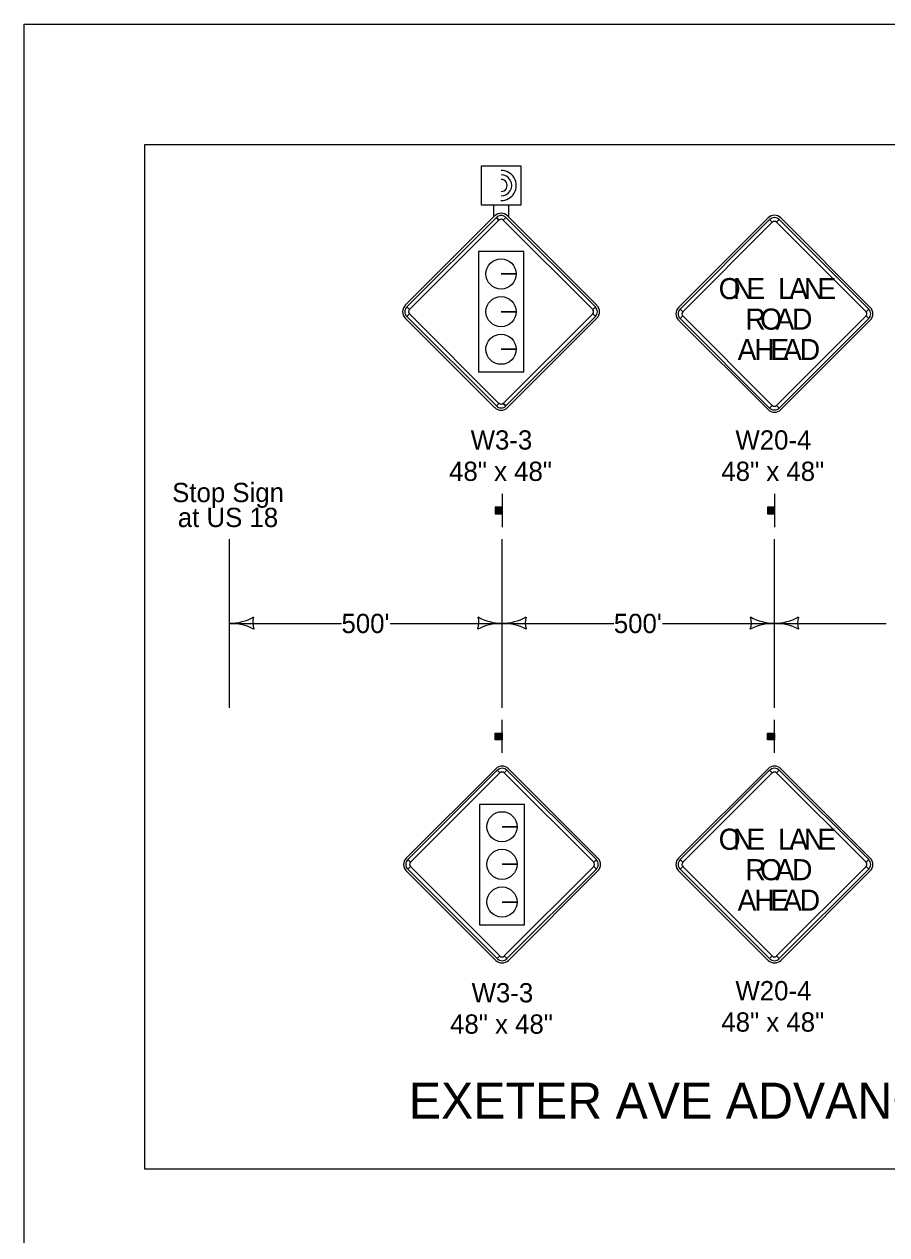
# Model space of a CAD drawing. Extents: x -2134934 to -2122394, y -2140205 to -2137036.
# Drawn here: x -2125529 to -2124814, y -2138041 to -2137036 of the extents above; entities that cross this region are included whole.
import ezdxf

# ---------------------------------------------------------------- set-up
doc = ezdxf.new("R2010")
doc.units = 0
for name, color, linetype in [('Barrier', 7, 'Continuous'), ('BridgeSuperStructureExisting', 7, 'Continuous'), ('Default', 7, 'Continuous')]:
    doc.layers.add(name, color=color, linetype=linetype)

msp = doc.modelspace()

# ---------------------------------------------------------------- linework, layer by layer
at = {"layer": 'Barrier'}
for p, q in [((-2125139.1, -2137195.1), (-2125213.3, -2137269.3)), ((-2125137.7, -2137196.4), (-2125135.5, -2137198.6)), ((-2125132, -2137198.6), (-2125129.8, -2137196.4)), ((-2125054.2, -2137269.3), (-2125128.4, -2137195.1)), ((-2124912.2, -2137196.8), (-2124986.5, -2137271.1)), ((-2124910.9, -2137198.1), (-2124908.7, -2137200.4)), ((-2124905.1, -2137200.4), (-2124902.9, -2137198.1)), ((-2124827.4, -2137271.1), (-2124901.6, -2137196.8)), ((-2125121.3, -2137243.3), (-2125133.8, -2137243.3)), ((-2125133.8, -2137243.3), (-2125121.3, -2137243.3)), ((-2125209.8, -2137272.9), (-2125212, -2137270.7)), ((-2125212, -2137278.6), (-2125209.8, -2137276.4)), ((-2125121.3, -2137274.6), (-2125133.8, -2137274.6)), ((-2125133.8, -2137274.6), (-2125121.3, -2137274.6)), ((-2125055.5, -2137270.7), (-2125057.7, -2137272.9)), ((-2125057.7, -2137276.4), (-2125055.5, -2137278.6)), ((-2124982.9, -2137274.6), (-2124985.1, -2137272.4)), ((-2124985.1, -2137280.3), (-2124982.9, -2137278.1)), ((-2124828.7, -2137272.4), (-2124830.9, -2137274.6)), ((-2124830.9, -2137278.1), (-2124828.7, -2137280.3)), ((-2125213.3, -2137280), (-2125139.1, -2137354.2)), ((-2125128.4, -2137354.2), (-2125054.2, -2137280)), ((-2124986.5, -2137281.7), (-2124912.2, -2137355.9)), ((-2124901.6, -2137355.9), (-2124827.4, -2137281.7)), ((-2125121.3, -2137305.8), (-2125133.8, -2137305.8)), ((-2125133.8, -2137305.8), (-2125121.3, -2137305.8)), ((-2125135.5, -2137350.7), (-2125137.7, -2137352.9)), ((-2125129.8, -2137352.9), (-2125132, -2137350.7)), ((-2124908.7, -2137352.4), (-2124910.9, -2137354.6)), ((-2124902.9, -2137354.6), (-2124905.1, -2137352.4)), ((-2125138.2, -2137654), (-2125212.5, -2137728.2)), ((-2125136.9, -2137655.3), (-2125134.7, -2137657.5)), ((-2125131.2, -2137657.5), (-2125129, -2137655.3)), ((-2125053.4, -2137728.2), (-2125127.6, -2137654)), ((-2124912.2, -2137654), (-2124986.5, -2137728.2)), ((-2124910.9, -2137655.3), (-2124908.7, -2137657.5)), ((-2124905.1, -2137657.5), (-2124902.9, -2137655.3)), ((-2124827.4, -2137728.2), (-2124901.6, -2137654)), ((-2125120.5, -2137702.2), (-2125133, -2137702.2)), ((-2125133, -2137702.2), (-2125120.5, -2137702.2)), ((-2125209, -2137731.7), (-2125211.2, -2137729.5)), ((-2125054.7, -2137729.5), (-2125056.9, -2137731.7)), ((-2124982.9, -2137731.7), (-2124985.1, -2137729.5)), ((-2124828.7, -2137729.5), (-2124830.9, -2137731.7)), ((-2125212.5, -2137738.8), (-2125138.2, -2137813.1)), ((-2125211.2, -2137737.5), (-2125209, -2137735.3)), ((-2125120.5, -2137733.4), (-2125133, -2137733.4)), ((-2125133, -2137733.4), (-2125120.5, -2137733.4)), ((-2125127.6, -2137813.1), (-2125053.4, -2137738.8)), ((-2125056.9, -2137735.3), (-2125054.7, -2137737.5)), ((-2124986.5, -2137738.8), (-2124912.2, -2137813.1)), ((-2124985.1, -2137737.5), (-2124982.9, -2137735.3)), ((-2124901.6, -2137813.1), (-2124827.4, -2137738.8)), ((-2124830.9, -2137735.3), (-2124828.7, -2137737.5)), ((-2125120.5, -2137764.7), (-2125133, -2137764.7)), ((-2125133, -2137764.7), (-2125120.5, -2137764.7)), ((-2125134.7, -2137809.5), (-2125136.9, -2137811.7)), ((-2125129, -2137811.7), (-2125131.2, -2137809.5)), ((-2124908.7, -2137809.5), (-2124910.9, -2137811.7)), ((-2124902.9, -2137811.7), (-2124905.1, -2137809.5))]:
    msp.add_line(p, q, dxfattribs=at)
for points in [[(-2125429.5, -2137135.9), (-2124308.2, -2137135.9), (-2124308.2, -2137986.6), (-2125429.5, -2137986.6)], [(-2125137.7, -2137196.4), (-2125212, -2137270.7), (-2125209.8, -2137272.9), (-2125135.5, -2137198.6), (-2125137.7, -2137196.4)], [(-2125055.5, -2137270.7), (-2125129.8, -2137196.4), (-2125132, -2137198.6), (-2125057.7, -2137272.9), (-2125055.5, -2137270.7)], [(-2124910.9, -2137198.1), (-2124985.1, -2137272.4), (-2124982.9, -2137274.6), (-2124908.7, -2137200.4), (-2124910.9, -2137198.1)], [(-2124828.7, -2137272.4), (-2124902.9, -2137198.1), (-2124905.1, -2137200.4), (-2124830.9, -2137274.6), (-2124828.7, -2137272.4)], [(-2125115, -2137224.7), (-2125152.5, -2137224.7), (-2125152.5, -2137324.6), (-2125115, -2137324.6), (-2125115, -2137224.7)], [(-2125212, -2137278.6), (-2125137.7, -2137352.9), (-2125135.5, -2137350.7), (-2125209.8, -2137276.4), (-2125212, -2137278.6)], [(-2125129.8, -2137352.9), (-2125055.5, -2137278.6), (-2125057.7, -2137276.4), (-2125132, -2137350.7), (-2125129.8, -2137352.9)], [(-2124985.1, -2137280.3), (-2124910.9, -2137354.6), (-2124908.7, -2137352.4), (-2124982.9, -2137278.1), (-2124985.1, -2137280.3)], [(-2124902.9, -2137354.6), (-2124828.7, -2137280.3), (-2124830.9, -2137278.1), (-2124905.1, -2137352.4), (-2124902.9, -2137354.6)], [(-2125136.9, -2137655.3), (-2125211.2, -2137729.5), (-2125209, -2137731.7), (-2125134.7, -2137657.5), (-2125136.9, -2137655.3)], [(-2125054.7, -2137729.5), (-2125129, -2137655.3), (-2125131.2, -2137657.5), (-2125056.9, -2137731.7), (-2125054.7, -2137729.5)], [(-2124910.9, -2137655.3), (-2124985.1, -2137729.5), (-2124982.9, -2137731.7), (-2124908.7, -2137657.5), (-2124910.9, -2137655.3)], [(-2124828.7, -2137729.5), (-2124902.9, -2137655.3), (-2124905.1, -2137657.5), (-2124830.9, -2137731.7), (-2124828.7, -2137729.5)], [(-2125114.2, -2137683.6), (-2125151.7, -2137683.6), (-2125151.7, -2137783.5), (-2125114.2, -2137783.5), (-2125114.2, -2137683.6)], [(-2125211.2, -2137737.5), (-2125136.9, -2137811.7), (-2125134.7, -2137809.5), (-2125209, -2137735.3), (-2125211.2, -2137737.5)], [(-2125129, -2137811.7), (-2125054.7, -2137737.5), (-2125056.9, -2137735.3), (-2125131.2, -2137809.5), (-2125129, -2137811.7)], [(-2124985.1, -2137737.5), (-2124910.9, -2137811.7), (-2124908.7, -2137809.5), (-2124982.9, -2137735.3), (-2124985.1, -2137737.5)], [(-2124902.9, -2137811.7), (-2124828.7, -2137737.5), (-2124830.9, -2137735.3), (-2124905.1, -2137809.5), (-2124902.9, -2137811.7)]]:
    msp.add_lwpolyline(points, close=True, dxfattribs=at)
for centre in [(-2125133.8, -2137243.3), (-2125133.8, -2137274.6), (-2125133.8, -2137305.8), (-2125133, -2137702.2), (-2125133, -2137733.4), (-2125133, -2137764.7)]:
    msp.add_circle(centre, 12.5, dxfattribs=at)
for centre, radius, start, end in [((-2125133.7, -2137200.4), 7.5, 45, 134.9997), ((-2125133.7, -2137200.4), 5.62, 45, 134.9997), ((-2125133.7, -2137200.4), 2.5, 45, 134.9997), ((-2124906.9, -2137202.1), 7.5, 45, 134.9997), ((-2124906.9, -2137202.1), 5.62, 45, 134.9997), ((-2124906.9, -2137202.1), 2.5, 45, 134.9997), ((-2125208, -2137274.7), 7.5, 134.9997, 225), ((-2125208, -2137274.7), 5.62, 134.9997, 225), ((-2125208, -2137274.7), 2.5, 134.9997, 225), ((-2125059.5, -2137274.7), 2.5, 315.0002, 44.9998), ((-2125059.5, -2137274.7), 5.62, 315.0002, 44.9998), ((-2125059.5, -2137274.7), 7.5, 315.0002, 44.9998), ((-2124981.2, -2137276.4), 7.5, 134.9997, 225), ((-2124981.2, -2137276.4), 5.62, 134.9997, 225), ((-2124981.2, -2137276.4), 2.5, 134.9997, 225), ((-2124832.7, -2137276.4), 2.5, 315.0002, 44.9998), ((-2124832.7, -2137276.4), 5.62, 315.0002, 44.9998), ((-2124832.7, -2137276.4), 7.5, 315.0002, 44.9998), ((-2125133.7, -2137348.9), 7.5, 225, 315.0002), ((-2125133.7, -2137348.9), 5.62, 225, 315.0002), ((-2125133.7, -2137348.9), 2.5, 225, 315.0002), ((-2124906.9, -2137350.6), 7.5, 225, 315.0002), ((-2124906.9, -2137350.6), 5.62, 225, 315.0002), ((-2124906.9, -2137350.6), 2.5, 225, 315.0002), ((-2125132.9, -2137659.3), 7.5, 45, 134.9997), ((-2125132.9, -2137659.3), 5.62, 45, 134.9997), ((-2125132.9, -2137659.3), 2.5, 45, 134.9997), ((-2124906.9, -2137659.3), 7.5, 45, 134.9997), ((-2124906.9, -2137659.3), 5.62, 45, 134.9997), ((-2124906.9, -2137659.3), 2.5, 45, 134.9997), ((-2125207.2, -2137733.5), 7.5, 134.9997, 225), ((-2125207.2, -2137733.5), 5.62, 134.9997, 225), ((-2125058.7, -2137733.5), 5.62, 315.0002, 44.9998), ((-2125058.7, -2137733.5), 7.5, 315.0002, 44.9998), ((-2124981.2, -2137733.5), 7.5, 134.9997, 225), ((-2124981.2, -2137733.5), 5.62, 134.9997, 225), ((-2124832.7, -2137733.5), 5.62, 315.0002, 44.9998), ((-2124832.7, -2137733.5), 7.5, 315.0002, 44.9998), ((-2125207.2, -2137733.5), 2.5, 134.9997, 225), ((-2125058.7, -2137733.5), 2.5, 315.0002, 44.9998), ((-2124981.2, -2137733.5), 2.5, 134.9997, 225), ((-2124832.7, -2137733.5), 2.5, 315.0002, 44.9998), ((-2125132.9, -2137807.8), 2.5, 225, 315.0002), ((-2124906.9, -2137807.8), 2.5, 225, 315.0002), ((-2125132.9, -2137807.8), 7.5, 225, 315.0002), ((-2125132.9, -2137807.8), 5.62, 225, 315.0002), ((-2124906.9, -2137807.8), 7.5, 225, 315.0002), ((-2124906.9, -2137807.8), 5.62, 225, 315.0002)]:
    msp.add_arc(centre, radius, start, end, dxfattribs=at)
at = {"layer": 'BridgeSuperStructureExisting'}
for p, q in [((-2125140, -2137186.1), (-2125140, -2137196.1)), ((-2125127.5, -2137186.1), (-2125127.5, -2137196.1)), ((-2125132.9, -2137425.9), (-2125132.9, -2137453.4)), ((-2124906.9, -2137425.9), (-2124906.9, -2137453.4)), ((-2125138.3, -2137436.8), (-2125138.3, -2137442.4)), ((-2125138, -2137442.4), (-2125138, -2137436.8)), ((-2125137.7, -2137436.8), (-2125137.7, -2137442.4)), ((-2125137.4, -2137442.4), (-2125137.4, -2137436.8)), ((-2125137.2, -2137436.8), (-2125137.2, -2137442.4)), ((-2125136.8, -2137442.4), (-2125136.8, -2137436.8)), ((-2125136.5, -2137436.8), (-2125136.5, -2137442.4)), ((-2125136.1, -2137442.4), (-2125136.1, -2137436.8)), ((-2125135.7, -2137436.8), (-2125135.7, -2137442.4)), ((-2125135.4, -2137442.4), (-2125135.4, -2137436.8)), ((-2125135.2, -2137436.8), (-2125135.2, -2137442.4)), ((-2125134.9, -2137442.4), (-2125134.9, -2137436.8)), ((-2125134.6, -2137436.8), (-2125134.6, -2137442.4)), ((-2125134.4, -2137442.4), (-2125134.4, -2137436.8)), ((-2125134.2, -2137436.8), (-2125134.2, -2137442.4)), ((-2125133.9, -2137442.4), (-2125133.9, -2137436.8)), ((-2125133.6, -2137436.8), (-2125133.6, -2137442.4)), ((-2125133.4, -2137442.4), (-2125133.4, -2137436.8)), ((-2124912.2, -2137436.8), (-2124912.2, -2137442.4)), ((-2124911.9, -2137442.4), (-2124911.9, -2137436.8)), ((-2124911.7, -2137436.8), (-2124911.7, -2137442.4)), ((-2124911.4, -2137442.4), (-2124911.4, -2137436.8)), ((-2124911.1, -2137436.8), (-2124911.2, -2137442.4)), ((-2124910.7, -2137442.4), (-2124910.7, -2137436.8)), ((-2124910.5, -2137436.8), (-2124910.5, -2137442.4)), ((-2124910.1, -2137442.4), (-2124910.1, -2137436.8)), ((-2124909.7, -2137436.8), (-2124909.7, -2137442.4)), ((-2124909.4, -2137442.4), (-2124909.4, -2137436.8)), ((-2124909.2, -2137436.8), (-2124909.2, -2137442.4)), ((-2124908.9, -2137442.4), (-2124908.9, -2137436.8)), ((-2124908.6, -2137436.8), (-2124908.6, -2137442.4)), ((-2124908.4, -2137442.4), (-2124908.4, -2137436.8)), ((-2124908.1, -2137436.8), (-2124908.1, -2137442.4)), ((-2124907.9, -2137442.4), (-2124907.9, -2137436.8)), ((-2124907.6, -2137436.8), (-2124907.6, -2137442.4)), ((-2124907.3, -2137442.4), (-2124907.3, -2137436.8)), ((-2125359, -2137603.4), (-2125359, -2137463.4)), ((-2125132.9, -2137603.4), (-2125132.9, -2137463.4)), ((-2124906.9, -2137603.4), (-2124906.9, -2137463.4)), ((-2125359, -2137533.4), (-2125266.2, -2137533.4)), ((-2125225.7, -2137533.4), (-2125132.9, -2137533.4)), ((-2125132.9, -2137533.4), (-2125040.2, -2137533.4)), ((-2124999.7, -2137533.4), (-2124906.9, -2137533.4)), ((-2124906.9, -2137533.4), (-2124814.1, -2137533.4)), ((-2125132.9, -2137640.9), (-2125132.9, -2137613.4)), ((-2124906.9, -2137640.9), (-2124906.9, -2137613.4)), ((-2125138.3, -2137630.1), (-2125138.3, -2137624.5)), ((-2125138, -2137624.5), (-2125138, -2137630.1)), ((-2125137.7, -2137630.1), (-2125137.7, -2137624.5)), ((-2125137.4, -2137624.5), (-2125137.4, -2137630.1)), ((-2125137.2, -2137630.1), (-2125137.2, -2137624.5)), ((-2125136.8, -2137624.5), (-2125136.8, -2137630.1)), ((-2125136.5, -2137630.1), (-2125136.5, -2137624.5)), ((-2125136.1, -2137624.5), (-2125136.1, -2137630.1)), ((-2125135.7, -2137630.1), (-2125135.7, -2137624.5)), ((-2125135.4, -2137624.5), (-2125135.4, -2137630.1)), ((-2125135.2, -2137630.1), (-2125135.2, -2137624.5)), ((-2125134.9, -2137624.5), (-2125134.9, -2137630.1)), ((-2125134.6, -2137630.1), (-2125134.6, -2137624.5)), ((-2125134.4, -2137624.5), (-2125134.4, -2137630.1)), ((-2125134.2, -2137630.1), (-2125134.2, -2137624.5)), ((-2125133.9, -2137624.5), (-2125133.9, -2137630.1)), ((-2125133.6, -2137630.1), (-2125133.6, -2137624.5)), ((-2125133.4, -2137624.5), (-2125133.4, -2137630.1)), ((-2124912.2, -2137630.1), (-2124912.2, -2137624.5)), ((-2124911.9, -2137624.5), (-2124911.9, -2137630.1)), ((-2124911.7, -2137630.1), (-2124911.7, -2137624.5)), ((-2124911.4, -2137624.5), (-2124911.4, -2137630.1)), ((-2124911.1, -2137630.1), (-2124911.2, -2137624.5)), ((-2124910.7, -2137624.5), (-2124910.7, -2137630.1)), ((-2124910.5, -2137630.1), (-2124910.5, -2137624.5)), ((-2124910.1, -2137624.5), (-2124910.1, -2137630.1)), ((-2124909.7, -2137630.1), (-2124909.7, -2137624.5)), ((-2124909.4, -2137624.5), (-2124909.4, -2137630.1)), ((-2124909.2, -2137630.1), (-2124909.2, -2137624.5)), ((-2124908.9, -2137624.5), (-2124908.9, -2137630.1)), ((-2124908.6, -2137630.1), (-2124908.6, -2137624.5)), ((-2124908.4, -2137624.5), (-2124908.4, -2137630.1)), ((-2124908.1, -2137630.1), (-2124908.1, -2137624.5)), ((-2124907.9, -2137624.5), (-2124907.9, -2137630.1)), ((-2124907.6, -2137630.1), (-2124907.6, -2137624.5)), ((-2124907.3, -2137624.5), (-2124907.3, -2137630.1))]:
    msp.add_line(p, q, dxfattribs=at)
for points in [[(-2125150, -2137186.1), (-2125150, -2137153.6), (-2125117.5, -2137153.6), (-2125117.5, -2137186.1)], [(-2125133, -2137442.4), (-2125133, -2137436.8), (-2125138.7, -2137436.8), (-2125138.7, -2137442.4)], [(-2124907, -2137442.4), (-2124907, -2137436.8), (-2124912.6, -2137436.8), (-2124912.6, -2137442.4)], [(-2125133, -2137624.5), (-2125133, -2137630.1), (-2125138.7, -2137630.1), (-2125138.7, -2137624.5)], [(-2124907, -2137624.5), (-2124907, -2137630.1), (-2124912.6, -2137630.1), (-2124912.6, -2137624.5)]]:
    msp.add_lwpolyline(points, close=True, dxfattribs=at)
for centre, radius, start, end in [((-2125133.7, -2137169.8), 12.5, 269.4041, 90.5445), ((-2125133.7, -2137169.8), 12.5, 269.4041, 90.5445), ((-2125133.7, -2137169.8), 8.75, 269.4041, 90.5445), ((-2125133.7, -2137169.8), 5, 269.4041, 90.5445), ((-2125359.7, -2137490.9), 42.5, 271.0176, 299.0725), ((-2125323.4, -2137532.8), 16.4, 163.2666, 198.7334), ((-2125168.6, -2137532.8), 16.4, 341.2666, 16.7334), ((-2125132.2, -2137490.9), 42.5, 240.9275, 268.9824), ((-2125133.7, -2137490.9), 42.5, 271.0176, 299.0725), ((-2125097.3, -2137532.8), 16.4, 163.2666, 198.7334), ((-2124942.5, -2137532.8), 16.4, 341.2666, 16.7334), ((-2124906.2, -2137490.9), 42.5, 240.9275, 268.9824), ((-2124907.7, -2137490.9), 42.5, 271.0176, 299.0725), ((-2124871.3, -2137532.8), 16.4, 163.2666, 198.7334), ((-2125358.3, -2137575.9), 42.5, 62.9275, 90.9824), ((-2125133.7, -2137575.9), 42.5, 89.0176, 117.0725), ((-2125132.2, -2137575.9), 42.5, 62.9275, 90.9824), ((-2124907.6, -2137575.9), 42.5, 89.0176, 117.0725), ((-2124906.2, -2137575.9), 42.5, 62.9275, 90.9824)]:
    msp.add_arc(centre, radius, start, end, dxfattribs=at)
at = {"layer": 'Default'}
msp.add_lwpolyline([(-2125529.5, -2137035.9), (-2122394.5, -2137035.9), (-2122394.5, -2139045.9), (-2125529.5, -2139045.9)], close=True, dxfattribs=at)

# ---------------------------------------------------------------- texts
at = {"layer": 'Barrier'}
for s, height, p in [('O', 17.5, (-2124953.2, -2137264.2)), ('N', 17.5, (-2124941.4, -2137264.2)), ('E', 17.5, (-2124930.2, -2137264.2)), ('L', 17.5, (-2124903.9, -2137264.2)), ('A', 17.5, (-2124894.7, -2137264.2)), ('N', 17.5, (-2124882.5, -2137264.2)), ('E', 17.5, (-2124871.2, -2137264.2)), ('R', 17.5, (-2124931.1, -2137289.5)), ('O', 17.5, (-2124918.8, -2137289.5)), ('A', 17.5, (-2124906, -2137289.5)), ('D', 17.5, (-2124892.3, -2137289.5)), ('A', 17.5, (-2124937.5, -2137314.8)), ('H', 17.5, (-2124923.7, -2137314.8)), ('E', 17.5, (-2124910.4, -2137314.8)), ('A', 17.5, (-2124899.7, -2137314.8)), ('D', 17.5, (-2124885.9, -2137314.8)), ('W3-3', 16, (-2125159, -2137389.1)), ('W20-4', 16, (-2124939.3, -2137389.1)), ('48" x 48"', 16, (-2125176.9, -2137415.1)), ('48" x 48"', 16, (-2124951, -2137415.1)), ('O', 17.5, (-2124953.2, -2137721.3)), ('N', 17.5, (-2124941.4, -2137721.3)), ('E', 17.5, (-2124930.2, -2137721.3)), ('L', 17.5, (-2124903.9, -2137721.3)), ('A', 17.5, (-2124894.7, -2137721.3)), ('N', 17.5, (-2124882.5, -2137721.3)), ('E', 17.5, (-2124871.2, -2137721.3)), ('R', 17.5, (-2124931.1, -2137746.6)), ('O', 17.5, (-2124918.8, -2137746.6)), ('A', 17.5, (-2124906, -2137746.6)), ('D', 17.5, (-2124892.3, -2137746.6)), ('A', 17.5, (-2124937.5, -2137771.9)), ('H', 17.5, (-2124923.7, -2137771.9)), ('E', 17.5, (-2124910.4, -2137771.9)), ('A', 17.5, (-2124899.7, -2137771.9)), ('D', 17.5, (-2124885.9, -2137771.9)), ('W20-4', 16, (-2124939.3, -2137846.3)), ('W3-3', 16, (-2125158.2, -2137848)), ('48" x 48"', 16, (-2125176.1, -2137874)), ('48" x 48"', 16, (-2124951, -2137872.3)), ('EXETER AVE ADVANCED SIGNING', 30, (-2125210.4, -2137944.6))]:
    msp.add_text(s, height=height, dxfattribs=at).set_placement(p)
at = {"layer": 'BridgeSuperStructureExisting'}
for s, p in [('Stop Sign', (-2125406.7, -2137432.7)), ('at US 18', (-2125402, -2137453.4)), ("500'", (-2125266.2, -2137541.4)), ("500'", (-2125040.2, -2137541.4))]:
    msp.add_text(s, height=16, dxfattribs=at).set_placement(p)

doc.saveas('drawing.dxf')
